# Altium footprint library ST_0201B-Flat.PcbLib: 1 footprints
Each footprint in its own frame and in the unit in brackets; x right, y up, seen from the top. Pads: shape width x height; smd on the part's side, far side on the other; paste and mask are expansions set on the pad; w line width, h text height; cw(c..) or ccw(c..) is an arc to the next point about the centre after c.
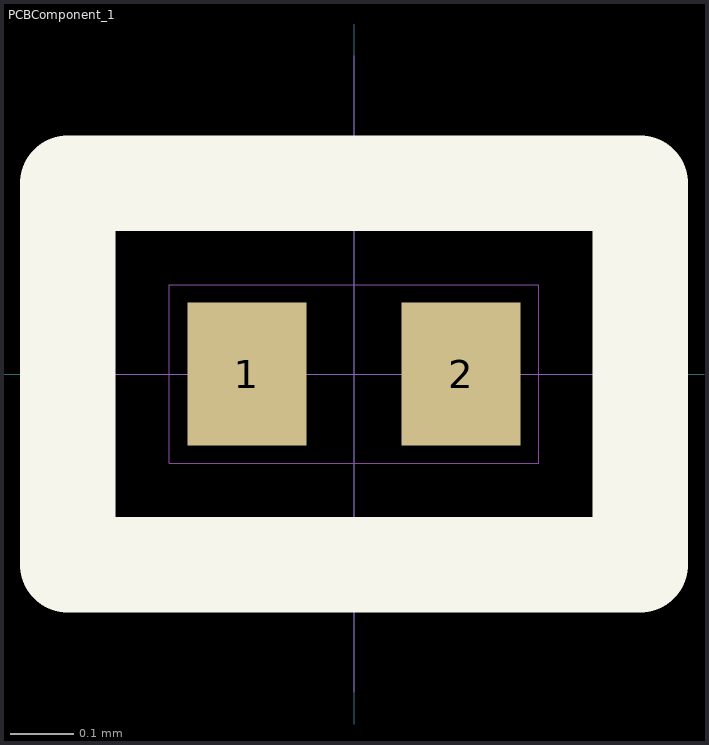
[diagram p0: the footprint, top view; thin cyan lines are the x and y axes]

## PCBComponent_1 [mm]
pads (2):
  rect 0.187x0.225 smd paste+0 mask+0.01: 1(-0.169,0) 2(0.169,0)
Top Overlay:
  lines w0.15: -0.45,-0.3 -0.45,0.3 0.45,0.3 0.45,-0.3 -0.45,-0.3
Mechanical 1:
  lines w0: -0.29,-0.14 -0.29,0.14 0.29,0.14 0.29,-0.14 -0.29,-0.14
Mechanical 15:
  lines w0.001: -0.5,0 0.5,0 ; 0,-0.5 0,0.5
3D body "ST_ST0201B-Flat.STEP": height 0.15, standoff 0, extent -0.29,-0.141 0.29,0.139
